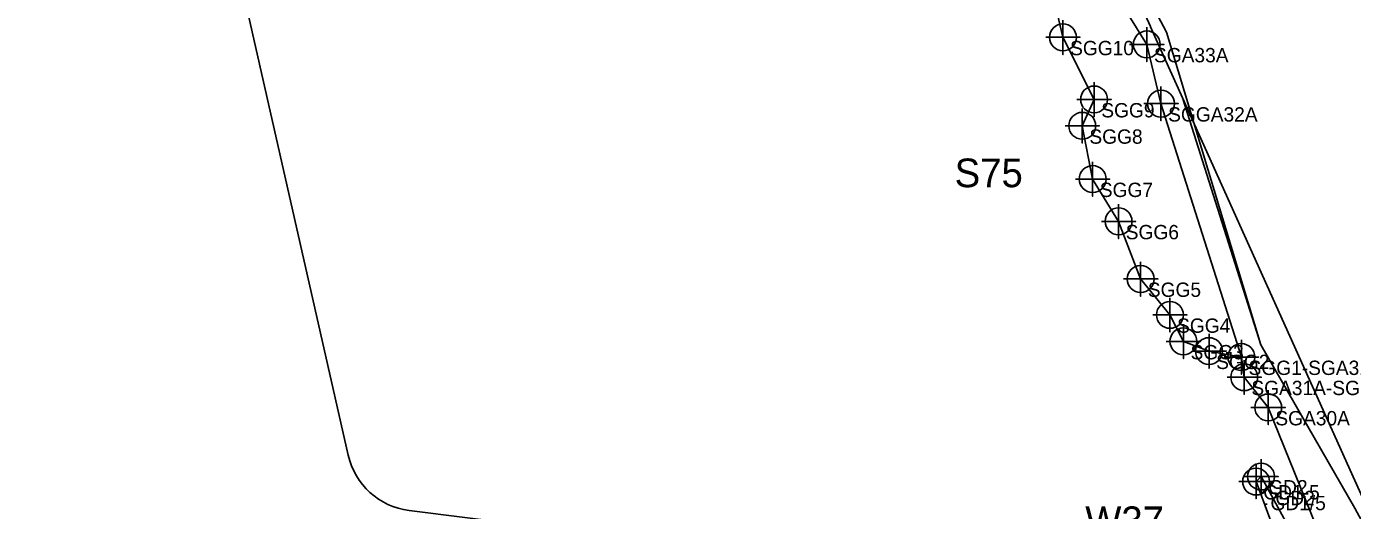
# Model space of a CAD drawing. Extents: x 1253697 to 1278588, y 912189 to 981699.
# Drawn here: x 1256788 to 1257713, y 947756 to 948094 of the extents above; entities that cross this region are included whole.
import ezdxf

# ---------------------------------------------------------------- set-up
doc = ezdxf.new("R2010")
doc.units = 0
for name, color, linetype in [('Default', 7, 'Continuous'), ('Exist Environmental Wetland Boundary', 7, 'Continuous'), ('Exist Environmental Wetland Boundary Cogo Comment', 7, 'Continuous'), ('Exist Environmental Wetland Boundary Cogo Number', 7, 'Continuous'), ('Exist Environmental Wetland Boundary Cogo Point CELL', 7, 'Continuous'), ('Exist Hydro Jurisdictional Stream or Body of Water Mitigable', 7, 'Continuous'), ('Exist Hydro Jurisdictional Stream or Body of Water Mitigable Cogo Comment', 7, 'Continuous'), ('Exist Hydro Jurisdictional Stream or Body of Water Mitigable Cogo Number', 7, 'Continuous'), ('Exist Hydro Jurisdictional Stream or Body of Water Mitigable Cogo Point CELL', 7, 'Continuous'), ('Exist Hydro Swamp or Marsh', 7, 'Continuous')]:
    doc.layers.add(name, color=color, linetype=linetype)

msp = doc.modelspace()

# ---------------------------------------------------------------- linework, layer by layer
at = {"layer": 'Default'}
for p, q in [((1257572.03, 948094.21), (1257565.87, 948107.84)), ((1257572.03, 948094.21), (1257565.87, 948107.84)), ((1257572.03, 948094.21), (1257565.87, 948107.84)), ((1257572.03, 948094.21), (1257565.87, 948107.84)), ((1257578.17, 948080.53), (1257572.09, 948094.09)), ((1257578.17, 948080.53), (1257572.09, 948094.09)), ((1257578.17, 948080.53), (1257572.09, 948094.09)), ((1257578.17, 948080.53), (1257572.09, 948094.09))]:
    msp.add_line(p, q, dxfattribs=at)
for points in [[(1256570.13, 948358.01), (1256893.36, 948318.45), (1257012.11, 947794.98)], [(1256570.13, 948358.01), (1256893.36, 948318.45), (1257012.11, 947794.98)], [(1256570.13, 948358.01), (1256893.36, 948318.45), (1257012.11, 947794.98)], [(1256570.13, 948358.01), (1256893.36, 948318.45), (1257012.11, 947794.98)], [(1257793.75, 947601.73), (1257590.17, 948053.64), (1257578.21, 948080.43)], [(1257793.75, 947601.73), (1257590.17, 948053.64), (1257578.21, 948080.43)], [(1257793.75, 947601.73), (1257590.17, 948053.64), (1257578.21, 948080.43)], [(1257793.75, 947601.73), (1257590.17, 948053.64), (1257578.21, 948080.43)], [(1257054.6, 947756.44), (1257280.4, 947727.93), (1257214.93, 947605.3)], [(1257054.6, 947756.44), (1257280.4, 947727.93), (1257214.93, 947605.3)], [(1257054.6, 947756.44), (1257280.4, 947727.93), (1257214.93, 947605.3)], [(1257054.6, 947756.44), (1257280.4, 947727.93), (1257214.93, 947605.3)]]:
    msp.add_lwpolyline(points, dxfattribs=at)
for centre, start, end in [((1257526.47, 948073.63), 24.1662, 24.31445), ((1257526.47, 948073.63), 24.1662, 24.31445), ((1257526.47, 948073.63), 24.1662, 24.31445), ((1257526.47, 948073.63), 24.1662, 24.31445), ((1257532.55, 948060.06), 24.04272, 24.1662), ((1257532.55, 948060.06), 24.04272, 24.1662), ((1257532.55, 948060.06), 24.04272, 24.1662), ((1257532.55, 948060.06), 24.04272, 24.1662), ((1257060.87, 947806.04), 192.78138, 262.80316), ((1257060.87, 947806.04), 192.78138, 262.80316), ((1257060.87, 947806.04), 192.78138, 262.80316), ((1257060.87, 947806.04), 192.78138, 262.80316)]:
    msp.add_arc(centre, 50, start, end, dxfattribs=at)
at = {"layer": 'Exist Environmental Wetland Boundary'}
msp.add_lwpolyline([(1257667.83, 947716.89), (1257645.81, 947776.63), (1257649.26, 947780.14), (1257681.24, 947721.5)], close=True, dxfattribs=at)
at = {"layer": 'Exist Environmental Wetland Boundary Cogo Point CELL'}
for points in [[(1257649.26, 947792.14), (1257649.26, 947768.14), (1257649.26, 947780.14), (1257661.26, 947780.14), (1257637.26, 947780.14)], [(1257645.81, 947788.63), (1257645.81, 947764.63), (1257645.81, 947776.63), (1257657.81, 947776.63), (1257633.81, 947776.63)]]:
    msp.add_lwpolyline(points, dxfattribs=at)
for centre in [(1257645.81, 947776.63), (1257649.26, 947780.14)]:
    msp.add_circle(centre, 9.38, dxfattribs=at)
at = {"layer": 'Exist Hydro Jurisdictional Stream or Body of Water Mitigable'}
for points in [[(1257691.43, 947736.3), (1257654.22, 947828.34), (1257637.49, 947849.45), (1257635.53, 947863.51), (1257579.4, 948040.39), (1257569.51, 948081.73), (1257520.9, 948160.28), (1257498.41, 948212.37), (1257460.31, 948217.34), (1257432.95, 948258.36), (1257414.16, 948296.25), (1257368.36, 948336.05), (1257344.74, 948369.72), (1257336.33, 948382.91), (1257287.28, 948410.45), (1257232.45, 948464.85), (1257198.08, 948521.71), (1257164.5, 948547.34), (1257138.54, 948567.21), (1257087.98, 948616.5), (1257033.25, 948653.61), (1256987.75, 948679.73), (1256934.27, 948708.66), (1256879.47, 948736.07)], [(1257388.67, 948340.96), (1257456.19, 948313.27), (1257509.11, 948230.33), (1257583.19, 948090.25), (1257649.21, 947872.03)], [(1257635.53, 947863.51), (1257612.93, 947867.66), (1257595.06, 947874.43), (1257585.63, 947892.95), (1257565.21, 947918), (1257549.78, 947958.22), (1257531.7, 947987.72), (1257524.42, 948024.9), (1257532.74, 948043.28), (1257510.96, 948086.68), (1257504.53, 948113.8), (1257494.47, 948120.09)], [(1257594.96, 948042.99), (1257649.21, 947872.03), (1257714.61, 947757.94), (1257747.07, 947698.26), (1257765.83, 947627.96), (1257803.67, 947571.26), (1257807.23, 947497.53), (1257840.32, 947452.51), (1257869.11, 947353.7), (1257904.76, 947297.44), (1257943.97, 947229.97), (1258002.47, 947171.11), (1258045.47, 947109.43), (1258085.72, 947072.72), (1258117.47, 947023.97), (1258128.6, 946988.72), (1258178.58, 946945.54)]]:
    msp.add_lwpolyline(points, dxfattribs=at)
at = {"layer": 'Exist Hydro Jurisdictional Stream or Body of Water Mitigable Cogo Point CELL'}
for points in [[(1257510.96, 948098.68), (1257510.96, 948074.68), (1257510.96, 948086.68), (1257522.96, 948086.68), (1257498.96, 948086.68)], [(1257569.51, 948093.73), (1257569.51, 948069.73), (1257569.51, 948081.73), (1257581.51, 948081.73), (1257557.51, 948081.73)], [(1257532.74, 948055.28), (1257532.74, 948031.28), (1257532.74, 948043.28), (1257544.74, 948043.28), (1257520.74, 948043.28)], [(1257579.4, 948052.39), (1257579.4, 948028.39), (1257579.4, 948040.39), (1257591.4, 948040.39), (1257567.4, 948040.39)], [(1257524.42, 948036.9), (1257524.42, 948012.9), (1257524.42, 948024.9), (1257536.42, 948024.9), (1257512.42, 948024.9)], [(1257531.7, 947999.72), (1257531.7, 947975.72), (1257531.7, 947987.72), (1257543.7, 947987.72), (1257519.7, 947987.72)], [(1257549.78, 947970.22), (1257549.78, 947946.22), (1257549.78, 947958.22), (1257561.78, 947958.22), (1257537.78, 947958.22)], [(1257565.21, 947930), (1257565.21, 947906), (1257565.21, 947918), (1257577.21, 947918), (1257553.21, 947918)], [(1257585.63, 947904.95), (1257585.63, 947880.95), (1257585.63, 947892.95), (1257597.63, 947892.95), (1257573.63, 947892.95)], [(1257595.06, 947886.43), (1257595.06, 947862.43), (1257595.06, 947874.43), (1257607.06, 947874.43), (1257583.06, 947874.43)], [(1257612.93, 947879.66), (1257612.93, 947855.66), (1257612.93, 947867.66), (1257624.93, 947867.66), (1257600.93, 947867.66)], [(1257635.53, 947875.51), (1257635.53, 947851.51), (1257635.53, 947863.51), (1257647.53, 947863.51), (1257623.53, 947863.51)], [(1257637.49, 947861.45), (1257637.49, 947837.45), (1257637.49, 947849.45), (1257649.49, 947849.45), (1257625.49, 947849.45)], [(1257654.22, 947840.34), (1257654.22, 947816.34), (1257654.22, 947828.34), (1257666.22, 947828.34), (1257642.22, 947828.34)]]:
    msp.add_lwpolyline(points, dxfattribs=at)
for centre in [(1257510.96, 948086.68), (1257569.51, 948081.73), (1257532.74, 948043.28), (1257579.4, 948040.39), (1257524.42, 948024.9), (1257531.7, 947987.72), (1257549.78, 947958.22), (1257565.21, 947918), (1257585.63, 947892.95), (1257595.06, 947874.43), (1257612.93, 947867.66), (1257635.53, 947863.51), (1257637.49, 947849.45), (1257654.22, 947828.34)]:
    msp.add_circle(centre, 9.38, dxfattribs=at)
at = {"layer": 'Exist Hydro Swamp or Marsh'}
msp.add_line((1257651.66, 947760.75), (1257653.56, 947760.75), dxfattribs=at)
msp.add_arc((1257663.2, 947754.69), 19.22, 122.12745, 137.23854, dxfattribs=at)

# ---------------------------------------------------------------- texts
at = {"layer": 'Exist Environmental Wetland Boundary Cogo Comment'}
for s, p in [('GD1/5', (1257655.81, 947756.63)), ('GD2', (1257659.26, 947760.14))]:
    msp.add_text(s, height=10, dxfattribs=at).set_placement(p)
at = {"layer": 'Exist Environmental Wetland Boundary Cogo Number'}
msp.add_text('W37', height=20, dxfattribs=at).set_placement((1257526.53, 947739.27))
at = {"layer": 'Exist Hydro Jurisdictional Stream or Body of Water Mitigable Cogo Comment'}
for s, p in [('SGG10', (1257515.96, 948074.18)), ('SGA33A', (1257574.51, 948069.23)), ('SGG9', (1257537.74, 948030.78)), ('SGGA32A', (1257584.4, 948027.89)), ('SGG8', (1257529.42, 948012.4)), ('SGG7', (1257536.7, 947975.22)), ('SGG6', (1257554.78, 947945.72)), ('SGG5', (1257570.21, 947905.5)), ('SGG4', (1257590.63, 947880.45)), ('SGG3', (1257600.06, 947861.93)), ('SGG2', (1257617.93, 947855.16)), ('SGG1-SGA31.5A', (1257640.53, 947851.01)), ('SGA31A-SGG1A', (1257642.49, 947836.95)), ('SGA30A', (1257659.22, 947815.84)), ('GD1-5', (1257650.81, 947764.13)), ('GD2', (1257654.26, 947767.64))]:
    msp.add_text(s, height=10, dxfattribs=at).set_placement(p)
at = {"layer": 'Exist Hydro Jurisdictional Stream or Body of Water Mitigable Cogo Number'}
msp.add_text('S75', height=20, dxfattribs=at).set_placement((1257435.38, 947982.06))

doc.saveas('drawing.dxf')
